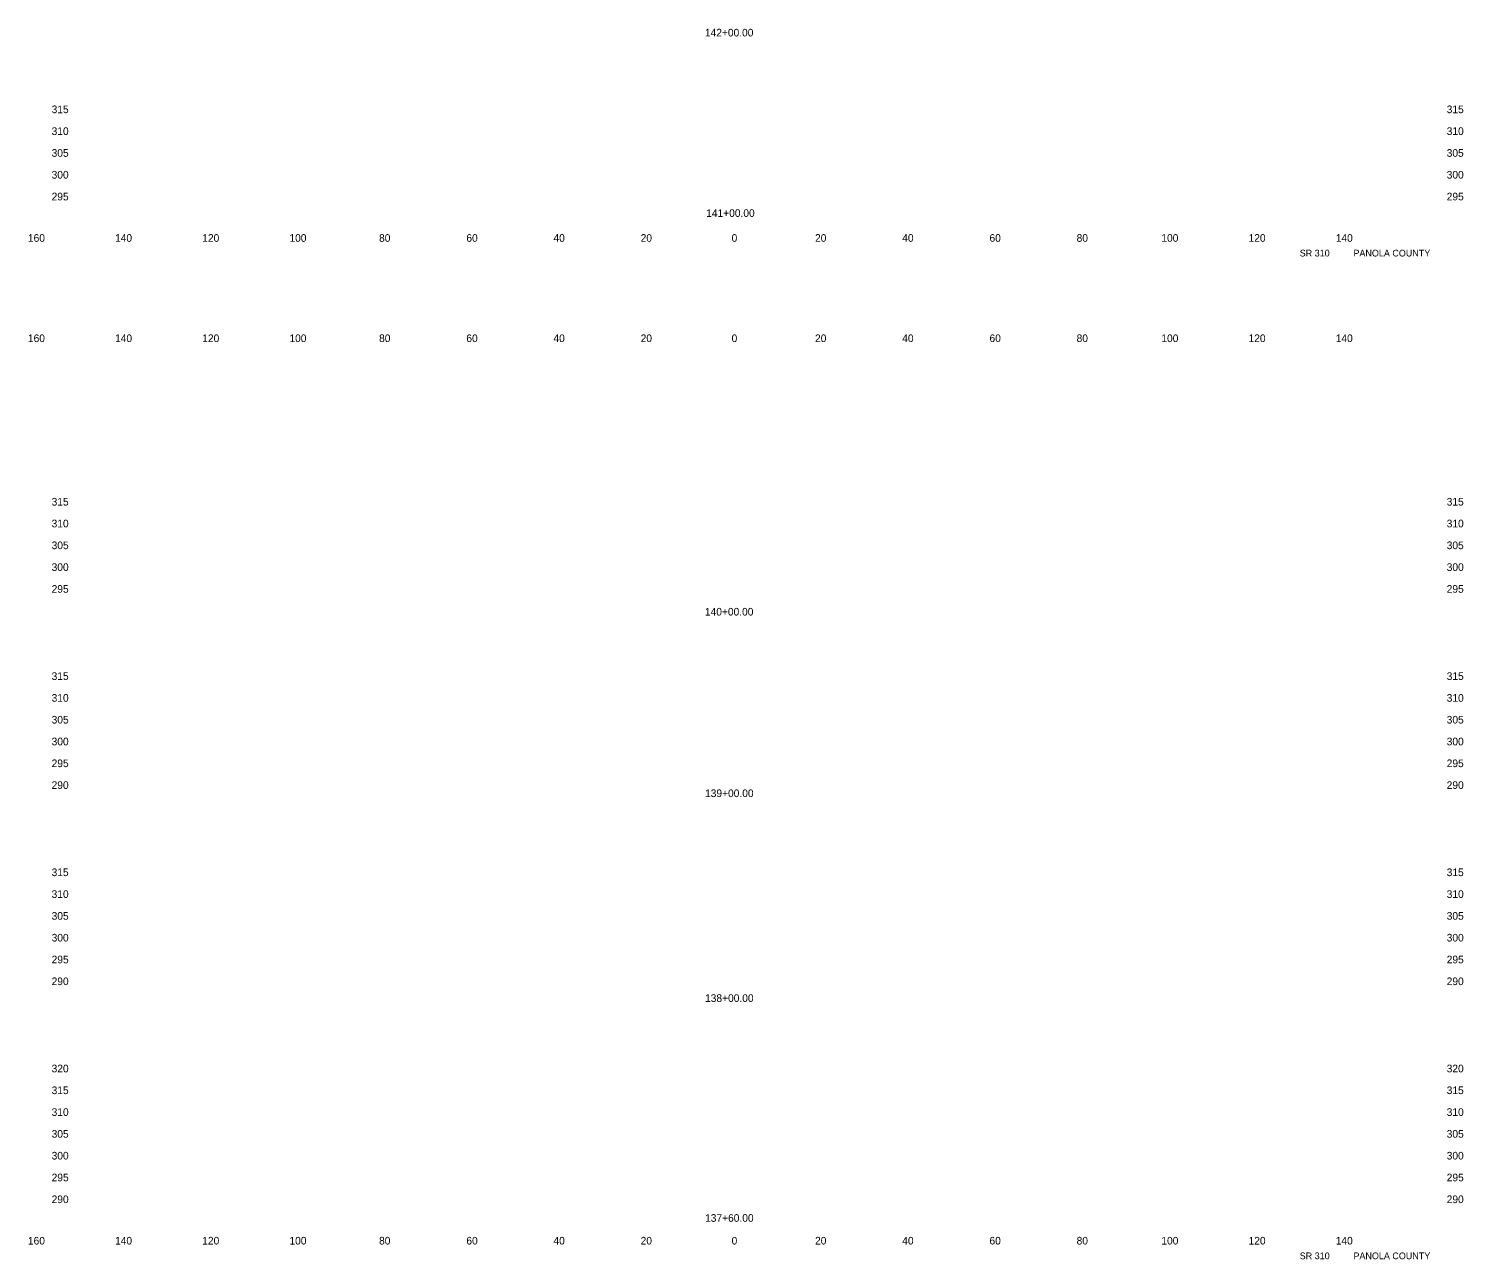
# Model space of a CAD drawing. Extents: x 21481 to 21810, y 6485 to 11067.
# Drawn here: x 21480.9 to 21809.9, y 9934.8 to 10217.1 of the extents above; entities that cross this region are included whole.
import ezdxf

# ---------------------------------------------------------------- set-up
doc = ezdxf.new("R2010")
doc.units = 0
for name, color, linetype in [('62', 7, 'Continuous'), ('XS_CELL', 7, 'Continuous'), ('XS_P_TX_DCH', 7, 'Continuous'), ('XS_P_TX_FS_BS', 7, 'Continuous')]:
    doc.layers.add(name, color=color, linetype=linetype)

msp = doc.modelspace()

# ---------------------------------------------------------------- texts
at = {"layer": '62'}
for s, p in [('  160  ', (21479.4, 10168.21)), ('  140  ', (21499.39, 10168.21)), ('  120  ', (21519.39, 10168.21)), ('  100  ', (21539.39, 10168.21)), ('  80  ', (21559.95, 10168.21)), ('  60  ', (21579.97, 10168.21)), ('  40  ', (21599.95, 10168.21)), ('  20  ', (21619.95, 10168.21)), ('  0  ', (21640.81, 10168.21)), ('  0  ', (21640.81, 10168.21)), ('  20  ', (21659.95, 10168.21)), ('  40  ', (21679.95, 10168.21)), ('  60  ', (21699.97, 10168.21)), ('  80  ', (21719.95, 10168.21)), ('  100  ', (21739.39, 10168.21)), ('  120  ', (21759.39, 10168.21)), ('  140  ', (21779.39, 10168.21)), ('  160  ', (21479.4, 10145.21)), ('  140  ', (21499.39, 10145.21)), ('  120  ', (21519.39, 10145.21)), ('  100  ', (21539.39, 10145.21)), ('  80  ', (21559.95, 10145.21)), ('  60  ', (21579.97, 10145.21)), ('  40  ', (21599.95, 10145.21)), ('  20  ', (21619.95, 10145.21)), ('  0  ', (21640.81, 10145.21)), ('  0  ', (21640.81, 10145.21)), ('  20  ', (21659.95, 10145.21)), ('  40  ', (21679.95, 10145.21)), ('  60  ', (21699.97, 10145.21)), ('  80  ', (21719.95, 10145.21)), ('  100  ', (21739.39, 10145.21)), ('  120  ', (21759.39, 10145.21)), ('  140  ', (21779.39, 10145.21)), ('  160  ', (21479.4, 9938.21)), ('  140  ', (21499.39, 9938.21)), ('  120  ', (21519.39, 9938.21)), ('  100  ', (21539.39, 9938.21)), ('  80  ', (21559.95, 9938.21)), ('  60  ', (21579.97, 9938.21)), ('  40  ', (21599.95, 9938.21)), ('  20  ', (21619.95, 9938.21)), ('  0  ', (21640.81, 9938.21)), ('  0  ', (21640.81, 9938.21)), ('  20  ', (21659.95, 9938.21)), ('  40  ', (21679.95, 9938.21)), ('  60  ', (21699.97, 9938.21)), ('  80  ', (21719.95, 9938.21)), ('  100  ', (21739.39, 9938.21)), ('  120  ', (21759.39, 9938.21)), ('  140  ', (21779.39, 9938.21))]:
    msp.add_text(s, height=1.75, dxfattribs=at).set_placement(p)
at = {"layer": 'XS_CELL'}
for s, p in [('  315  ', (21484.84, 10197.71)), ('  315  ', (21804.84, 10197.71)), ('  310  ', (21484.84, 10192.71)), ('  310  ', (21804.84, 10192.71)), ('  305  ', (21484.84, 10187.71)), ('  305  ', (21804.84, 10187.71)), ('  300  ', (21484.84, 10182.71)), ('  300  ', (21804.84, 10182.71)), ('  295  ', (21484.84, 10177.71)), ('  295  ', (21804.84, 10177.71)), ('  315  ', (21484.84, 10107.71)), ('  315  ', (21804.84, 10107.71)), ('  310  ', (21484.84, 10102.71)), ('  310  ', (21804.84, 10102.71)), ('  305  ', (21484.84, 10097.71)), ('  305  ', (21804.84, 10097.71)), ('  300  ', (21484.84, 10092.71)), ('  300  ', (21804.84, 10092.71)), ('  295  ', (21484.84, 10087.71)), ('  295  ', (21804.84, 10087.71)), ('  315  ', (21484.84, 10067.71)), ('  315  ', (21804.84, 10067.71)), ('  310  ', (21484.84, 10062.71)), ('  310  ', (21804.84, 10062.71)), ('  305  ', (21484.84, 10057.71)), ('  305  ', (21804.84, 10057.71)), ('  300  ', (21484.84, 10052.71)), ('  300  ', (21804.84, 10052.71)), ('  295  ', (21484.84, 10047.71)), ('  295  ', (21804.84, 10047.71)), ('  290  ', (21484.84, 10042.71)), ('  290  ', (21804.84, 10042.71)), ('  315  ', (21484.84, 10022.71)), ('  315  ', (21804.84, 10022.71)), ('  310  ', (21484.84, 10017.71)), ('  310  ', (21804.84, 10017.71)), ('  305  ', (21484.84, 10012.71)), ('  305  ', (21804.84, 10012.71)), ('  300  ', (21484.84, 10007.71)), ('  300  ', (21804.84, 10007.71)), ('  295  ', (21484.84, 10002.71)), ('  295  ', (21804.84, 10002.71)), ('  290  ', (21484.84, 9997.71)), ('  290  ', (21804.84, 9997.71)), ('  320  ', (21484.84, 9977.71)), ('  320  ', (21804.84, 9977.71)), ('  315  ', (21484.84, 9972.71)), ('  315  ', (21804.84, 9972.71)), ('  310  ', (21484.84, 9967.71)), ('  310  ', (21804.84, 9967.71)), ('  305  ', (21484.84, 9962.71)), ('  305  ', (21804.84, 9962.71)), ('  300  ', (21484.84, 9957.71)), ('  300  ', (21804.84, 9957.71)), ('  295  ', (21484.84, 9952.71)), ('  295  ', (21804.84, 9952.71)), ('  290  ', (21484.84, 9947.71)), ('  290  ', (21804.84, 9947.71))]:
    msp.add_text(s, height=1.75, dxfattribs=at).set_placement(p)
at = {"layer": 'XS_P_TX_DCH'}
for s, p in [('  142+00.00  ', (21634.69, 10215.31)), ('  141+00.00  ', (21634.98, 10173.92)), ('  140+00.00  ', (21634.69, 10082.48)), ('  139+00.00  ', (21634.72, 10040.84)), ('  138+00.00  ', (21634.72, 9993.86)), ('  137+60.00  ', (21634.73, 9943.42))]:
    msp.add_text(s, height=1.75, dxfattribs=at).set_placement(p)
at = {"layer": 'XS_P_TX_FS_BS'}
for s, p in [('SR 310', (21772.43, 10164.84)), ('SR 310', (21772.43, 10164.84)), ('SR 310', (21772.43, 10164.84)), ('PANOLA COUNTY', (21784.75, 10164.84)), ('PANOLA COUNTY', (21784.75, 10164.84)), ('PANOLA COUNTY', (21784.75, 10164.84)), ('SR 310', (21772.43, 9934.84)), ('SR 310', (21772.43, 9934.84)), ('SR 310', (21772.43, 9934.84)), ('PANOLA COUNTY', (21784.75, 9934.84)), ('PANOLA COUNTY', (21784.75, 9934.84)), ('PANOLA COUNTY', (21784.75, 9934.84))]:
    msp.add_text(s, height=1.54, dxfattribs=at).set_placement(p)

doc.saveas('drawing.dxf')
